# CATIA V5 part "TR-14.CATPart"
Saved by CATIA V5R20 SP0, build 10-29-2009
Part number: _TR-14
Definition: NONE
Nomenclature: _TR-14
Source: Unknown
Description: PART-_TR-14-DESC
Bounding box of the stored display mesh (mm): x 0 to 12.5, y -7.9 to 7.9, z -7.9 to 7.9
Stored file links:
  C:\Users\Utente\Desktop\IO LAVORO\3D X SITO CF\X SITO\PLASTICA\TR\TR-14.CATPart
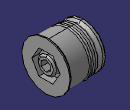
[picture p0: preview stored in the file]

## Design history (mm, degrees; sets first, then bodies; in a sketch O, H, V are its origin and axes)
Body1 "_TR-14" (main body)
  Solid1: solid without history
